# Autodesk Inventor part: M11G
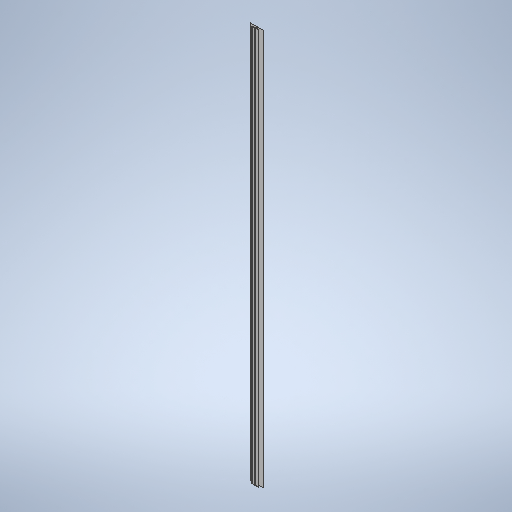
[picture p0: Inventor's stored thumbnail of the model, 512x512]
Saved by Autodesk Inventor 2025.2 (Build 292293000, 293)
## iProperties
Created: 2024-10
Part Number: M11G
Material: Generic
Document SubType Name: Modeling
Designer: MACMetalTech
Density: 1 g/cm^3
Appearance: Default
Author: MACMetalTech
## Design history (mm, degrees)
sketch "Sketch1"
  geometry: L1 (1.016, 0)-(50.546, 0); L2 (50.546, 0)-(50.546, 0.508); L3 (1.016, 0.508)-(50.546, 0.508); L4 (0, 1.016)-(0, 13.716); L5 (1.016, 14.732)-(22.86, 14.732); L6 (22.86, 14.732)-(22.86, 14.224); L7 (22.86, 14.224)-(1.016, 14.224); L8 (0.508, 13.716)-(0.508, 1.016); L9 (-0.508, 1.016)-(-0.508, 13.716); L10 (-1.524, 14.732)-(-23.368, 14.732); L11 (-23.368, 14.732)-(-23.368, 14.224); L12 (-1.524, 14.224)-(-23.368, 14.224); L13 (-1.524, 0)-(-51.054, 0); L14 (-51.054, 0)-(-51.054, 0.508); L15 (-51.054, 0.508)-(-1.524, 0.508); L16 (-1.016, 1.016)-(-1.016, 13.716); L17 (23.876, 13.716)-(3.683, 13.716); L18 (3.683, 13.716)-(3.683, 13.208); L19 (3.683, 13.208)-(23.876, 13.208); L20 (-24.384, 13.716)-(-4.191, 13.716); L21 (-4.191, 13.716)-(-4.191, 13.208); L22 (-4.191, 13.208)-(-24.384, 13.208); L23 (-24.384, 15.24)-(23.876, 15.24); L24 (23.876, 15.748)-(-24.384, 15.748); L25 (25.146, 14.478)-(-25.654, 14.478); L26 (-0.254, 14.478)-(-0.254, 0); L27 (0, 0)-(-0.508, 0); A1 r 0.762 centre (23.876, 14.478) between (23.876, 13.716) and (23.876, 15.24); A2 r 1.27 centre (23.876, 14.478) between (23.876, 13.208) and (23.876, 15.748); A3 r 0.762 centre (-24.384, 14.478) between (-24.384, 15.24) and (-24.384, 13.716); A4 r 1.27 centre (-24.384, 14.478) between (-24.384, 15.748) and (-24.384, 13.208); A5 r 0.508 centre (1.016, 1.016) between (0.508, 1.016) and (1.016, 0.508); A6 r 0.508 centre (-1.524, 1.016) between (-1.524, 0.508) and (-1.016, 1.016); A7 r 0.508 centre (1.016, 13.716) between (1.016, 14.224) and (0.508, 13.716); A8 r 0.508 centre (-1.524, 13.716) between (-1.016, 13.716) and (-1.524, 14.224); A9 r 1.016 centre (1.016, 13.716) between (1.016, 14.732) and (0, 13.716); A10 r 1.016 centre (-1.524, 13.716) between (-0.508, 13.716) and (-1.524, 14.732); A11 r 1.016 centre (-1.524, 1.016) between (-1.524, 0) and (-0.508, 1.016); A12 r 1.016 centre (1.016, 1.016) between (0, 1.016) and (1.016, 0); 6 further points
  constraints: 54 end point, 26 point on circle, 21 tangent, 16 point on line, 12 centre point, 10 perpendicular, 8 horizontal, 6 equal radius, 4 collinear, 3 vertical, 2 coincident, 2 midpoint, 2 parallel
  dimensions: "d1" = 50.546 distance of L27.start L1.end; "d2" = 0.508 distance of L1.end L2.end; "d4" = 0.508 distance of L5.end L6.end; "d5" = 0.508 distance between parallel lines of L4 L8; "d6" = 0.508 distance of L27.start L27.end; "d8" = 50.546 distance of L27.end L13.end; "d9" = 0.508 distance between parallel lines of L9 L16; "d10" = 0.508 distance between parallel lines of L10 L12; "d12" = 2.54 diameter of A2; "d13" = 1.524 diameter of A3; "d14" = 2.54 diameter of A4; "d15" = 3.175 distance between parallel lines of L18 L8; "d16" = 3.175 distance between parallel lines of L16 L21; "d17" = 0.508 distance between parallel lines of L13 L15; "d19" = 0.508 distance between parallel lines of L23 L10; "d20" = 12.7 distance between parallel lines of L3 L19; "d21" = 50.8 distance of L25.end L25.start; "d22" = 1.016 distance from line of A1.centre L6; "d23" = 1.016 distance from line of L11 A3.centre; "d26" = 0.508 radius of A5; "d27" = 1.016 radius of A9
extrude "Extrusion1" new body sketch "Sketch1" distance "d24" = 3048; taper "d25" = 0 deg
body "Solid1"
